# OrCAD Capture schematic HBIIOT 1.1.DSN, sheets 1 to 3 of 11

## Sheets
1 POWER: size C; title: POWER; rev: 2.5.0
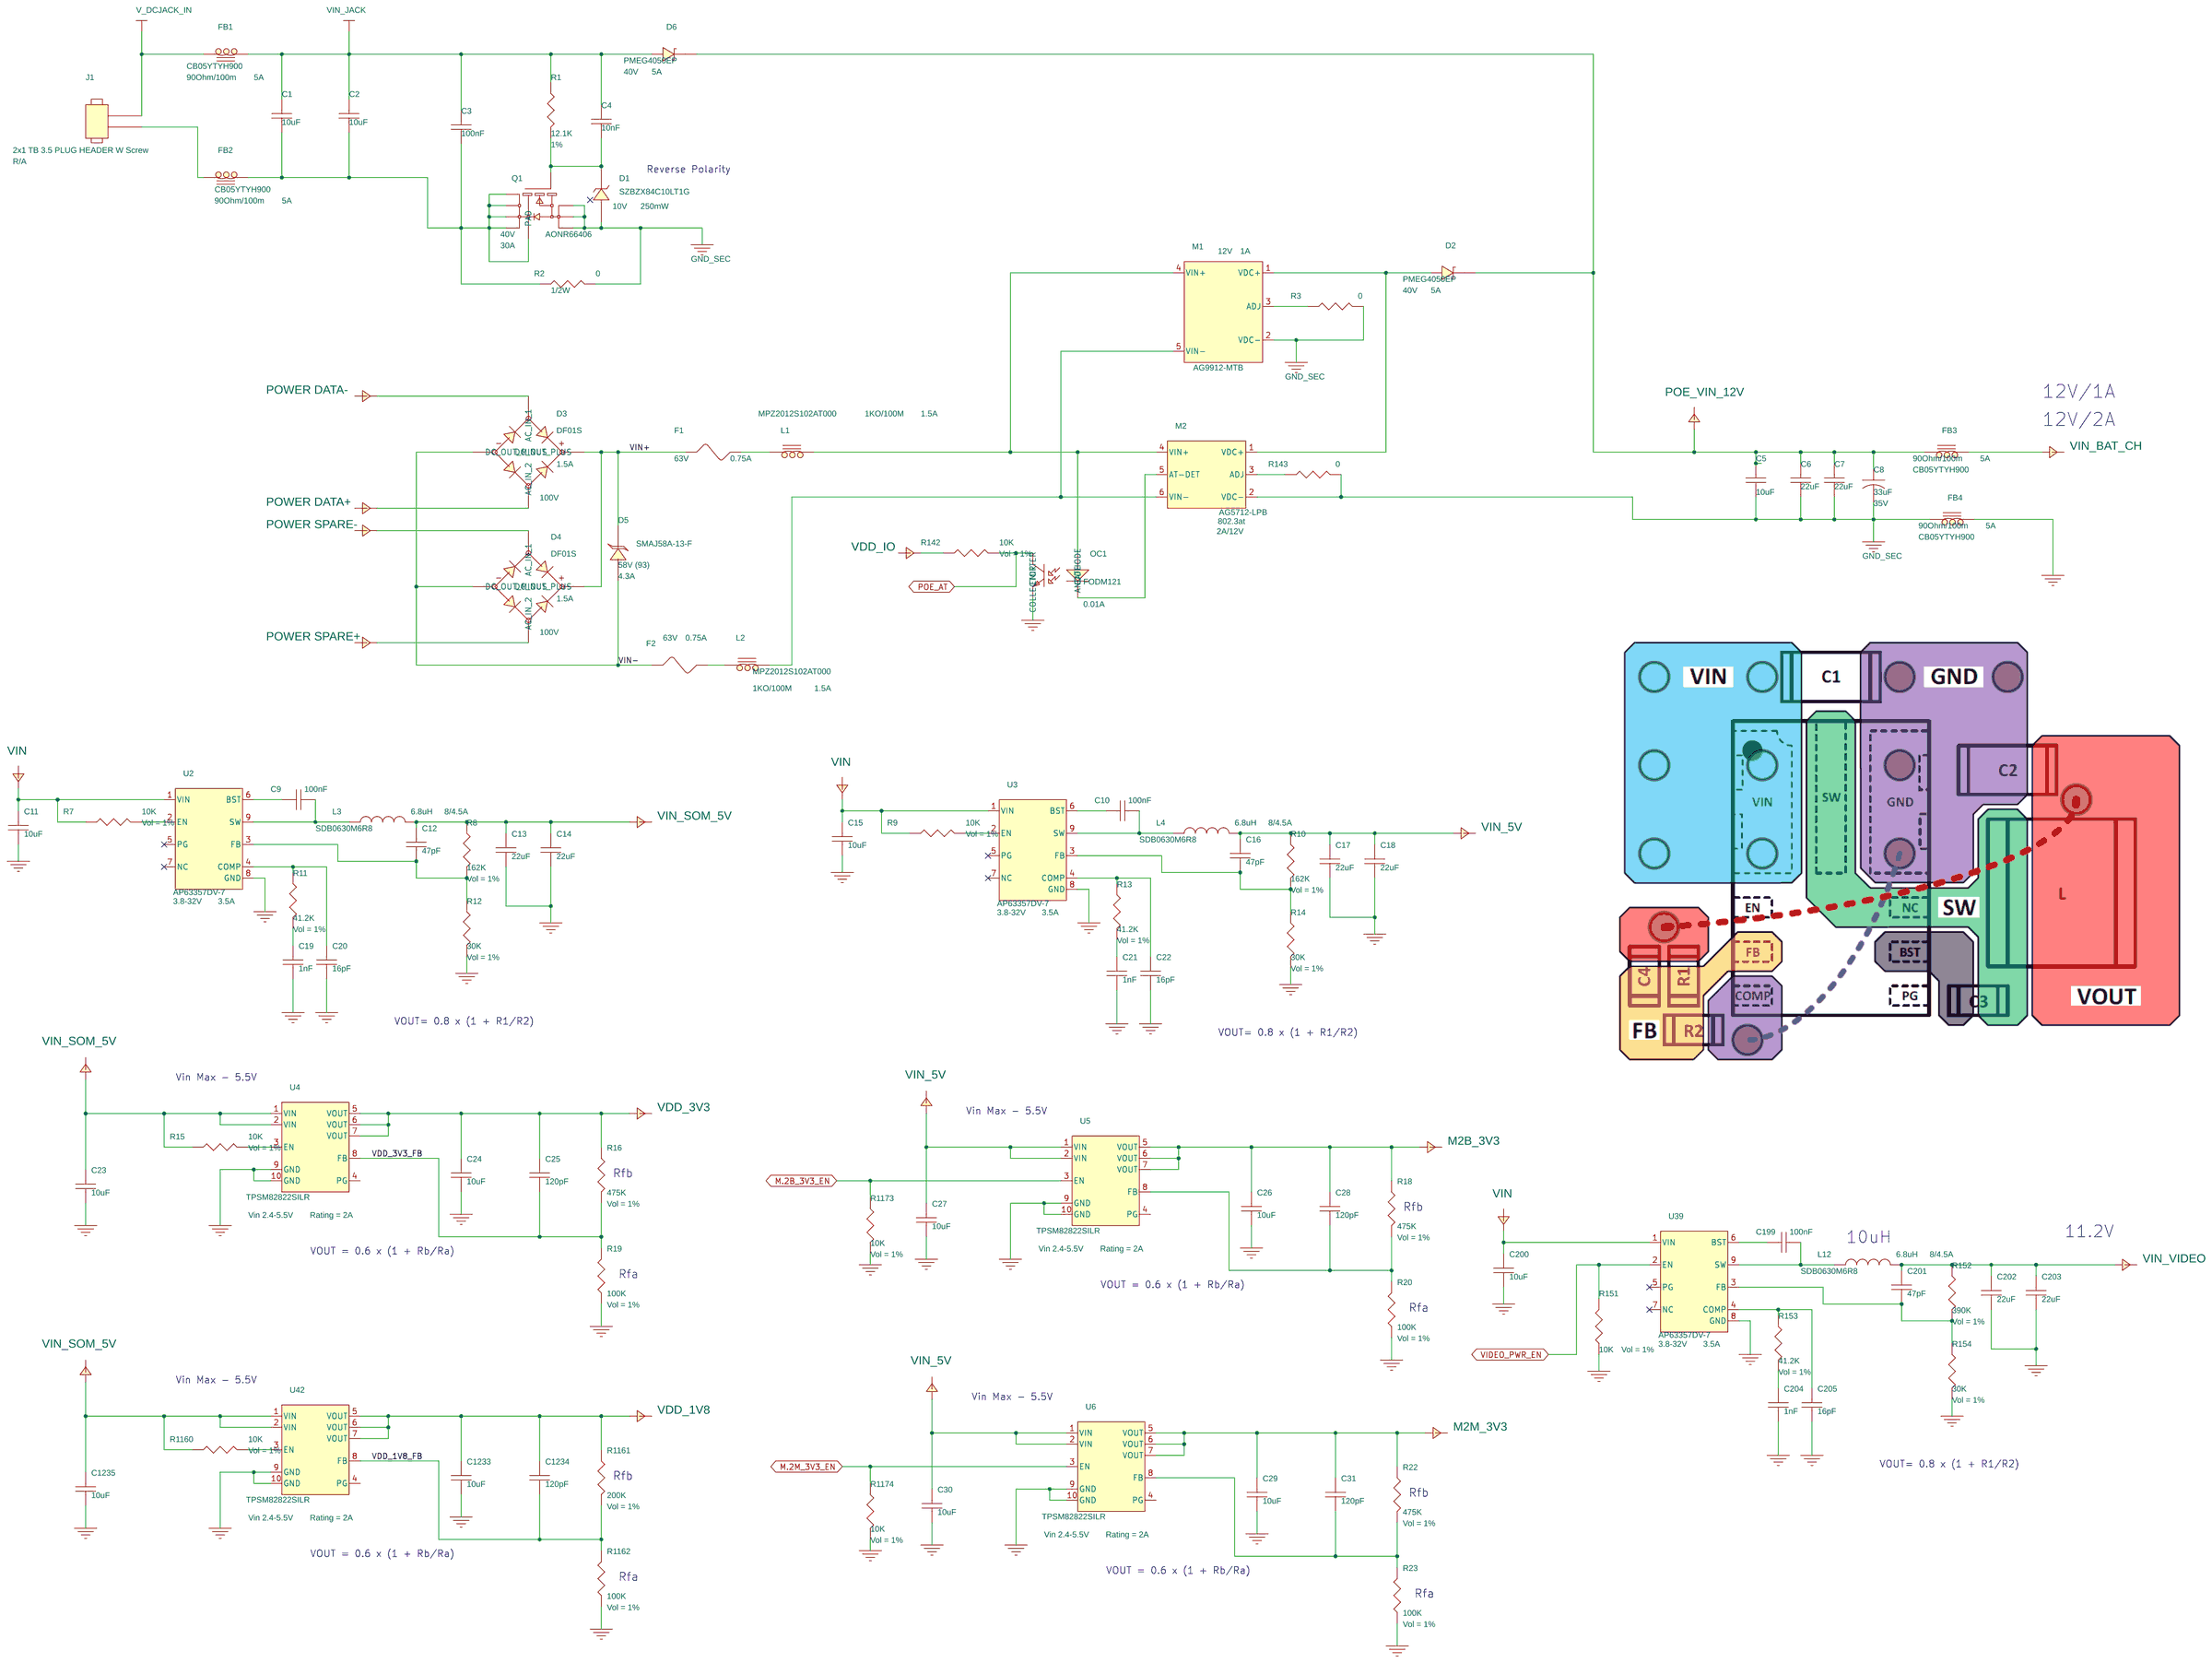
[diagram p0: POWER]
2 SYSTEM, ETHERNET, UART: size A3; title: SYSTEM,  DEBUG, uSD, EEPROM
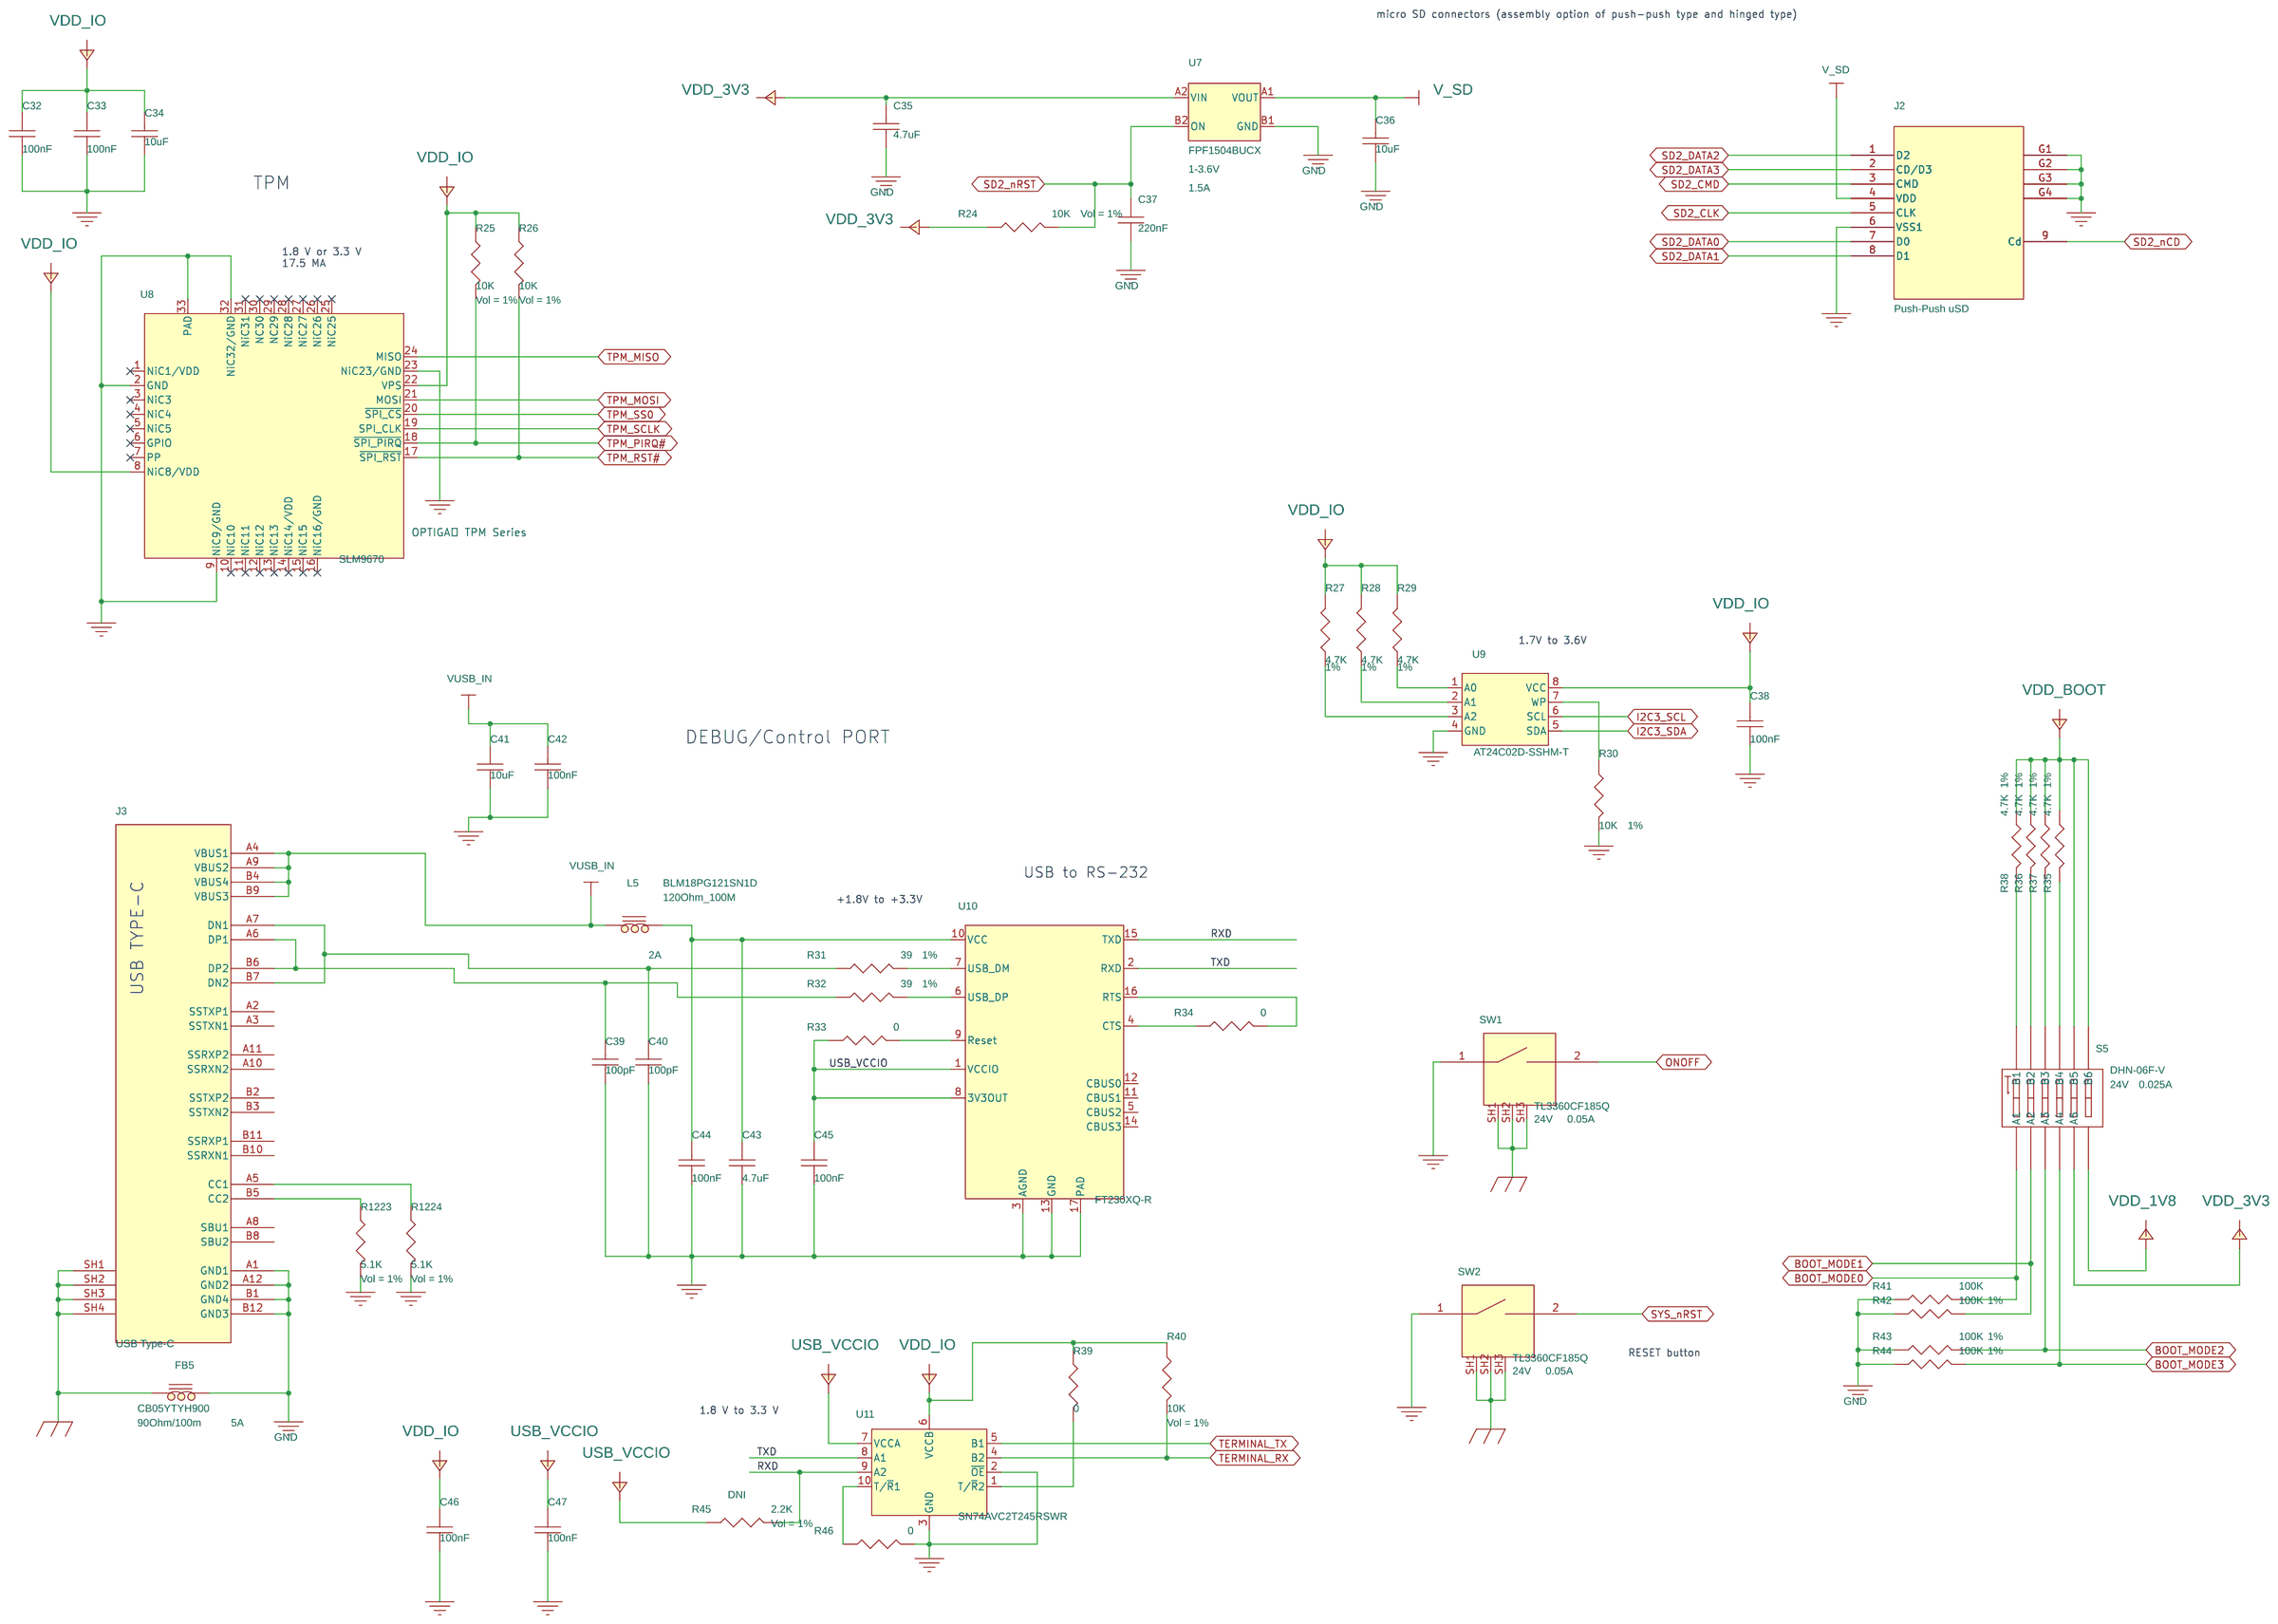
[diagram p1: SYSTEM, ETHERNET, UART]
3 USB3 HUB: size C; title: USB-3 HIB; rev: 2.4.0
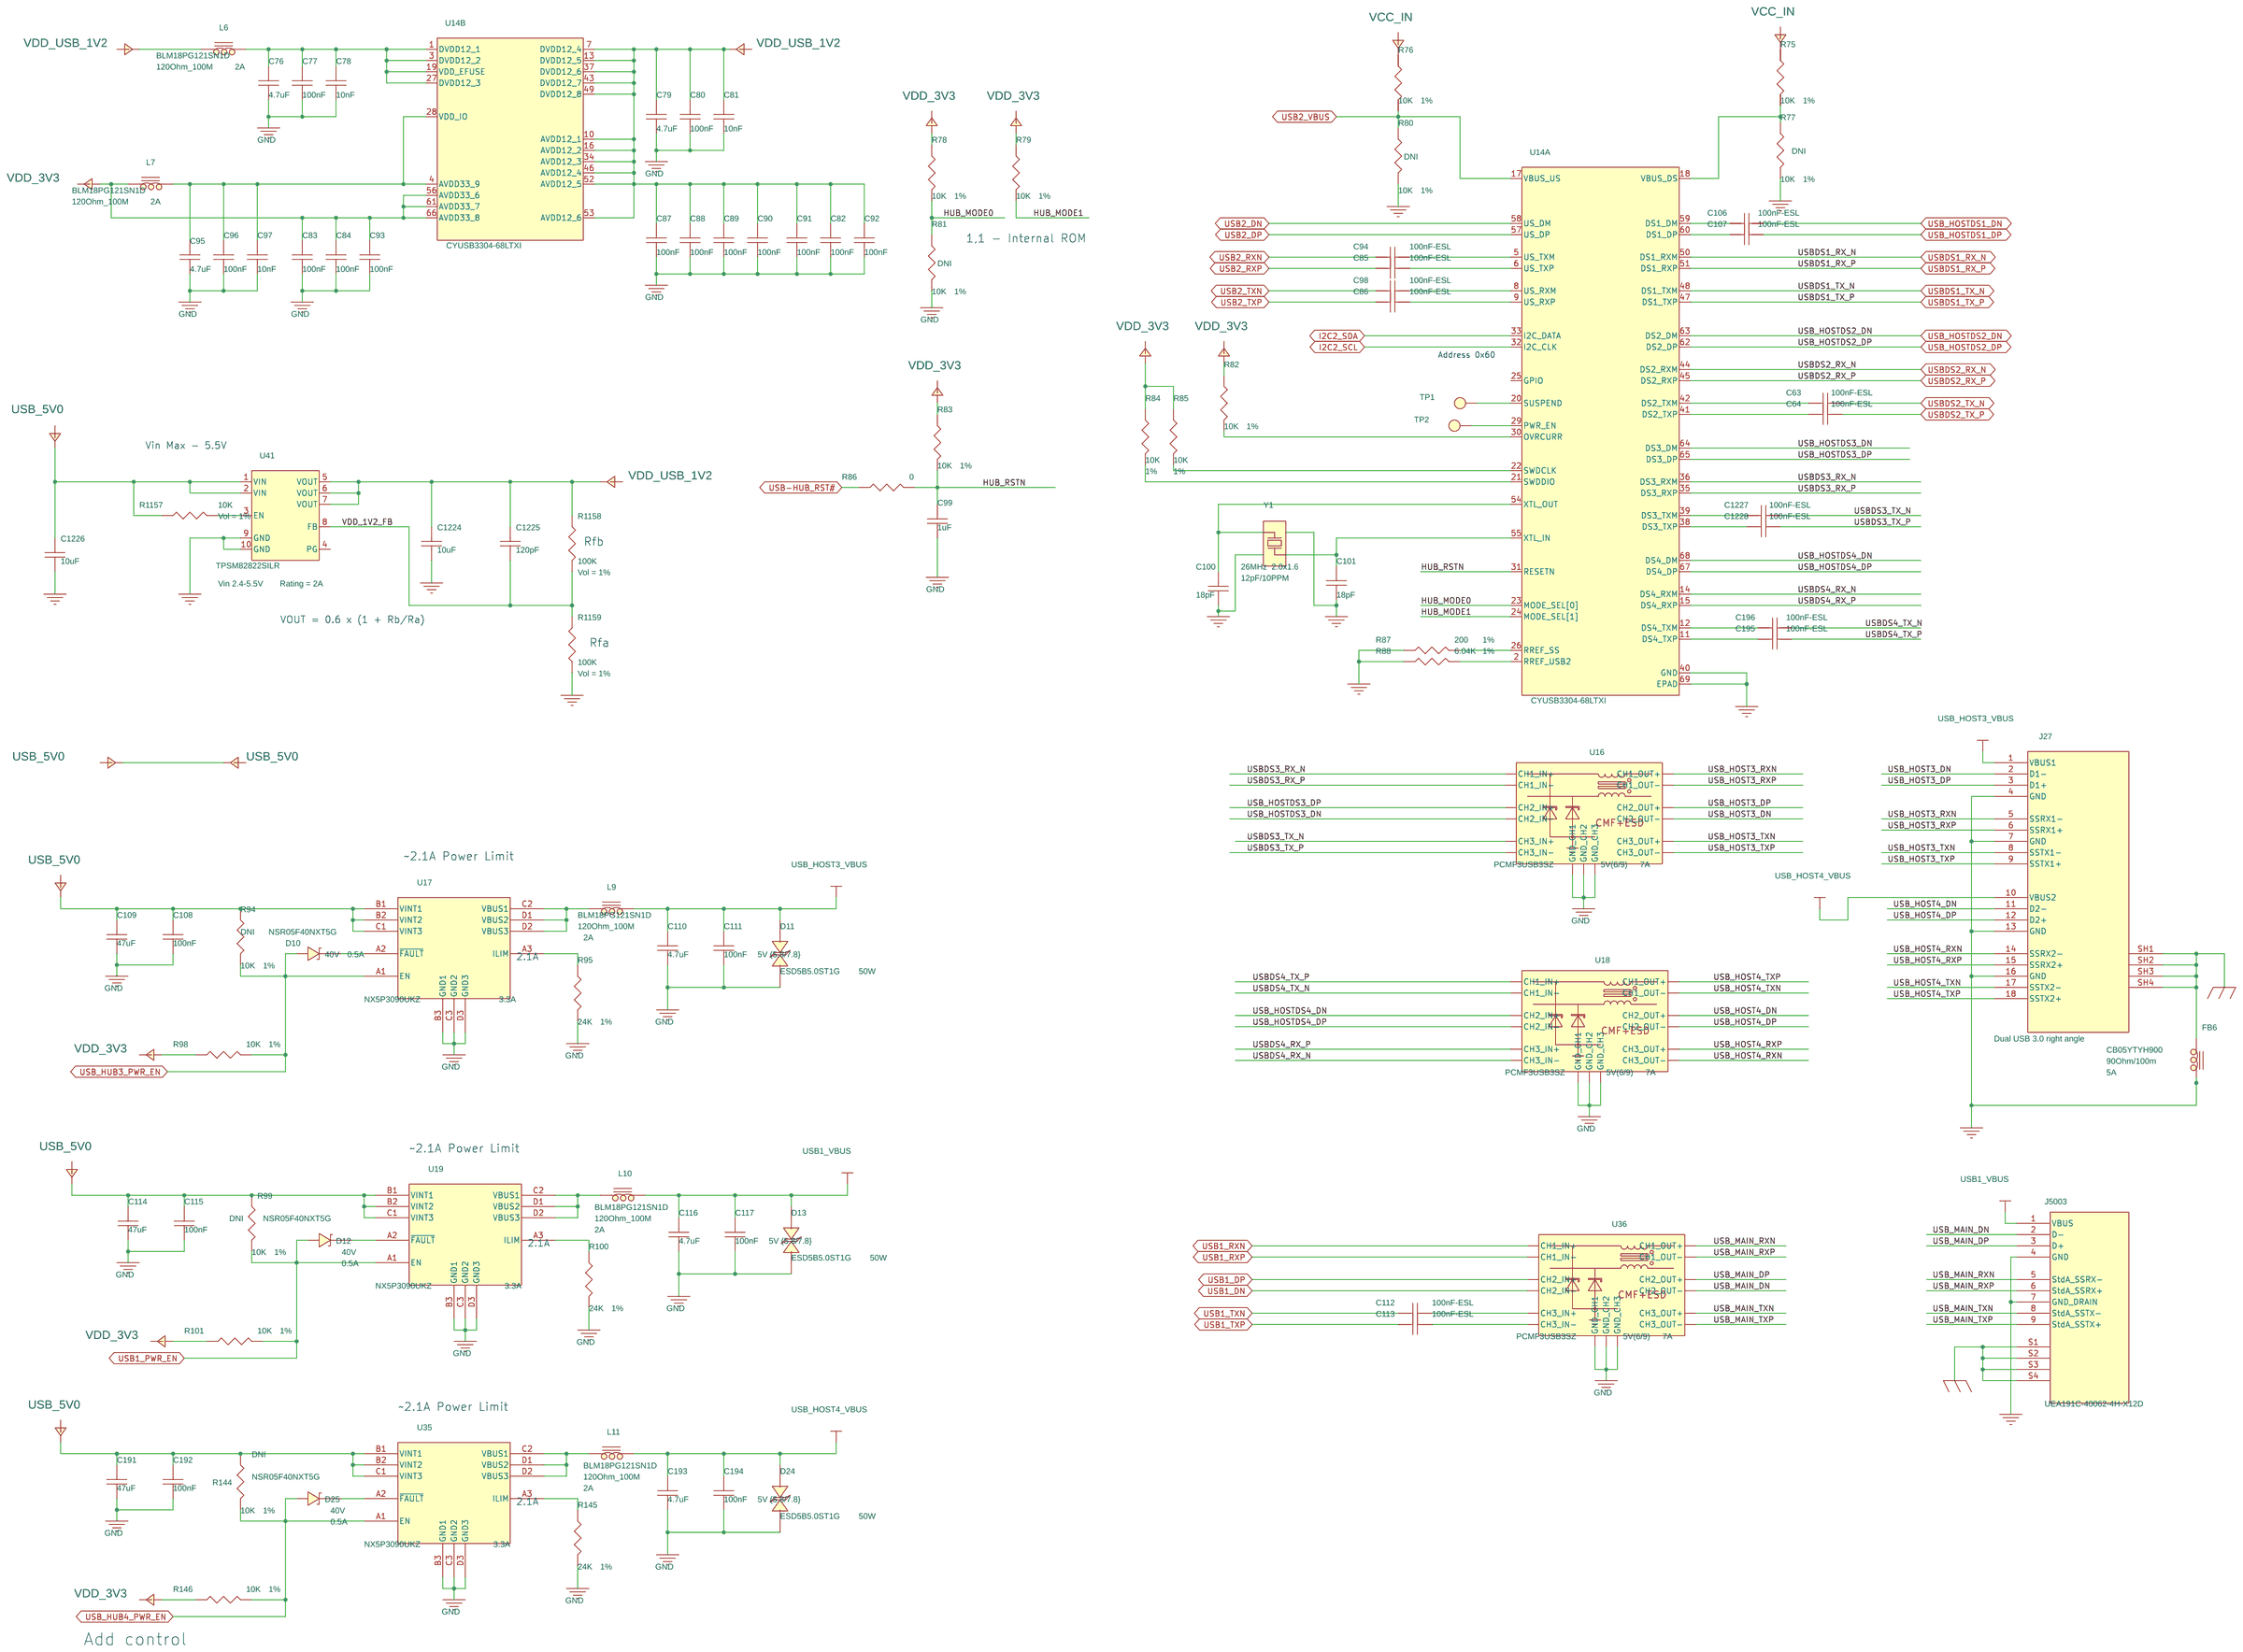
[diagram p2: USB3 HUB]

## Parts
sheet POWER
C1  10uF  [C1206]
C2  10uF  [C1206]
C3  100nF  [C0402]
C4  10nF  [C0402]
C5  10uF  [C0805]
C6  22uF  [C0805]
C7  22uF  [C0805]
C8  33uF  [EEE-FP1E330AP]
C9  100nF  [C0402]
C10  100nF  [C0402]
C11  10uF  [C1206]
C12  47pF  [C0402]
C13  22uF  [C0805]
C14  22uF  [C0805]
C15  10uF  [C1206]
C16  47pF  [C0402]
C17  22uF  [C0805]
C18  22uF  [C0805]
C19  1nF  [C0402]
C20  16pF  [C0402]
C21  1nF  [C0402]
C22  16pF  [C0402]
C23  10uF  [C0402]
C24  10uF  [C0402]
C25  120pF  [C0402]
C26  10uF  [C0402]
C27  10uF  [C0402]
C28  120pF  [C0402]
C29  10uF  [C0402]
C30  10uF  [C0402]
C31  120pF  [C0402]
C199  100nF  [C0402]
C200  10uF  [C1206]
C201  47pF  [C0402]
C202  22uF  [C0805]
C203  22uF  [C0805]
C204  1nF  [C0402]
C205  16pF  [C0402]
C1233  10uF  [C0402]
C1234  120pF  [C0402]
C1235  10uF  [C0402]
D1  SZBZX84C10LT1G  [SZBZX84C10LT1G]
D2  PMEG4050EP  [PMEG4050EP]
D3  DF01S  [DF01S]
D4  DF01S  [DF01S]
D5  SMAJ58A-13-F  [SMAJ58A-13-F]
D6  PMEG4050EP  [PMEG4050EP]
F1  63V  [0437.750WR]
F2  63V  [0437.750WR]
FB1  CB05YTYH900  [CB05YTYH900]
FB2  CB05YTYH900  [CB05YTYH900]
FB3  CB05YTYH900  [CB05YTYH900]
FB4  CB05YTYH900  [CB05YTYH900]
J1  2x1 TB 3.5 PLUG HEADER W Screw  [691325110002]
L1  MPZ2012S102AT000  [MPZ2012S102AT000]
L2  MPZ2012S102AT000  [MPZ2012S102AT000]
L3  SDB0630M6R8  [SDB0630M6R8]
L4  SDB0630M6R8  [SDB0630M6R8]
L12  SDB0630M6R8  [SDB0630M6R8]
M1  AG9912-MTB  [AG9912-MTB]
M2  AG5712-LPB  [AG5712-LPB]
OC1  FODM121  [FODM121]
Q1  AONR66406  [AONR66406]
R1  12.1K  [R0402]
R2  0  [R0603]
R3  0  [R0402]
R7  10K  [R0402]
R8  162K  [R0402]
R9  10K  [R0402]
R10  162K  [R0402]
R11  41.2K  [R0402]
R12  30K  [R0402]
R13  41.2K  [R0402]
R14  30K  [R0402]
R15  10K  [R0402]
R16  475K  [R0402]
R18  475K  [R0402]
R19  100K  [R0402]
R20  100K  [R0402]
R22  475K  [R0402]
R23  100K  [R0402]
R142  10K  [R0402]
R143  0  [R0402]
R151  10K  [R0402]
R152  390K  [R0402]
R153  41.2K  [R0402]
R154  30K  [R0402]
R1160  10K  [R0402]
R1161  200K  [R0402]
R1162  100K  [R0402]
R1173  10K  [R0402]
R1174  10K  [R0402]
U2  AP63357DV-7  [AP63357DV-7]
U3  AP63357DV-7  [AP63357DV-7]
U4  TPSM82822SILR  [TPSM82822SILR]
U5  TPSM82822SILR  [TPSM82822SILR]
U6  TPSM82822SILR  [TPSM82822SILR]
U39  AP63357DV-7  [AP63357DV-7]
U42  TPSM82822SILR  [TPSM82822SILR]
sheet SYSTEM, ETHERNET, UART
C32  100nF  [C0402]
C33  100nF  [C0402]
C34  10uF  [C0402]
C35  4.7uF  [C0402]
C36  10uF  [C0603]
C37  220nF  [C0402]
C38  100nF  [C0402]
C39  100pF  [C0402]
C40  100pF  [C0402]
C41  10uF  [C0603]
C42  100nF  [C0402]
C43  4.7uF  [C0603]
C44  100nF  [C0402]
C45  100nF  [C0402]
C46  100nF  [C0402]
C47  100nF  [C0402]
FB5  CB05YTYH900  [CB05YTYH900]
J2  Push-Push uSD  [ZM90-15000-0BR1]
J3  USB Type-C  [1054500101]
L5  BLM18PG121SN1D  [BLM18PG121SN1D]
R24  10K  [R0402]
R25  10K  [R0402]
R26  10K  [R0402]
R27  4.7K  [R0402]
R28  4.7K  [R0402]
R29  4.7K  [R0402]
R30  10K  [R0402]
R31  39  [R0402]
R32  39  [R0402]
R33  0  [R0402]
R34  0  [R0402]
R35  4.7K  [R0402]
R36  4.7K  [R0402]
R37  4.7K  [R0402]
R38  4.7K  [R0402]
R39  0  [R0402]
R40  10K  [R0402]
R41  100K  [R0402]
R42  100K  [R0402]
R43  100K  [R0402]
R44  100K  [R0402]
R45  2.2K  [R0402]
R46  0  [R0402]
R1223  5.1K  [R0402]
R1224  5.1K  [R0402]
S5  DHN-06F-V  [DHN-06F-V]
SW1  TL3360CF185Q  [TL3360CF185Q]
SW2  TL3360CF185Q  [TL3360CF185Q]
U7  FPF1504BUCX  [FPF1504BUCX]
U8  SLM9670  [SLM9670]
U9  AT24C02D-SSHM-T  [AT24C02D-SSHM-B]
U10  FT230XQ-R  [FT230XQ-R]
U11  SN74AVC2T245RSWR  [SN74AVC2T245RSWR]
sheet USB3 HUB
C63  100nF-ESL  [C0402]
C64  100nF-ESL  [C0402]
C76  4.7uF  [C0603]
C77  100nF  [C0402]
C78  10nF  [C0402]
C79  4.7uF  [C0603]
C80  100nF  [C0402]
C81  10nF  [C0402]
C82  100nF  [C0402]
C83  100nF  [C0402]
C84  100nF  [C0402]
C85  100nF-ESL  [C0402]
C86  100nF-ESL  [C0402]
C87  100nF  [C0402]
C88  100nF  [C0402]
C89  100nF  [C0402]
C90  100nF  [C0402]
C91  100nF  [C0402]
C92  100nF  [C0402]
C93  100nF  [C0402]
C94  100nF-ESL  [C0402]
C95  4.7uF  [C0603]
C96  100nF  [C0402]
C97  10nF  [C0402]
C98  100nF-ESL  [C0402]
C99  1uF  [C0402]
C100  18pF  [C0402]
C101  18pF  [C0402]
C106  100nF-ESL  [C0402]
C107  100nF-ESL  [C0402]
C108  100nF  [C0402]
C109  47uF  [C1206]
C110  4.7uF  [C0603]
C111  100nF  [C0402]
C112  100nF-ESL  [C0402]
C113  100nF-ESL  [C0402]
C114  47uF  [C1206]
C115  100nF  [C0402]
C116  4.7uF  [C0603]
C117  100nF  [C0402]
C191  47uF  [C1206]
C192  100nF  [C0402]
C193  4.7uF  [C0603]
C194  100nF  [C0402]
C195  100nF-ESL  [C0402]
C196  100nF-ESL  [C0402]
C1224  10uF  [C0402]
C1225  120pF  [C0402]
C1226  10uF  [C0402]
C1227  100nF-ESL  [C0402]
C1228  100nF-ESL  [C0402]
D10  NSR05F40NXT5G  [NSR05F40NXT5G]
D11  ESD5B5.0ST1G  [ESD5B5.0ST1G]
D12  NSR05F40NXT5G  [NSR05F40NXT5G]
D13  ESD5B5.0ST1G  [ESD5B5.0ST1G]
D24  ESD5B5.0ST1G  [ESD5B5.0ST1G]
D25  NSR05F40NXT5G  [NSR05F40NXT5G]
FB6  CB05YTYH900  [CB05YTYH900]
J27  Dual USB 3.0 right angle  [U3AFR03-B-P/L-B-G0-A]
J5003  UEA191C-40062-4H-X12D  [UEA191C-40062-4H-X12D]
L6  BLM18PG121SN1D  [BLM18PG121SN1D]
L7  BLM18PG121SN1D  [BLM18PG121SN1D]
L9  BLM18PG121SN1D  [BLM18PG121SN1D]
L10  BLM18PG121SN1D  [BLM18PG121SN1D]
L11  BLM18PG121SN1D  [BLM18PG121SN1D]
R75  10K  [R0402]
R76  10K  [R0402]
R77  10K  [R0402]
R78  10K  [R0402]
R79  10K  [R0402]
R80  10K  [R0402]
R81  10K  [R0402]
R82  10K  [R0402]
R83  10K  [R0402]
R84  10K  [R0402]
R85  10K  [R0402]
R86  0  [R0402]
R87  200  [R0402]
R88  6.04K  [R0402]
R94  10K  [R0402]
R95  24K  [R0402]
R98  10K  [R0402]
R99  10K  [R0402]
R100  24K  [R0402]
R101  10K  [R0402]
R144  10K  [R0402]
R145  24K  [R0402]
R146  10K  [R0402]
R1157  10K  [R0402]
R1158  100K  [R0402]
R1159  100K  [R0402]
TP1  R 35
TP2  R 35
U14  CYUSB3304-68LTXI  [CYUSB3304-68LTXI]  (sections A,B)
U16  PCMF3USB3SZ  [PCMF3USB3SZ]
U17  NX5P3090UKZ  [NX5P3090UKZ]
U18  PCMF3USB3SZ  [PCMF3USB3SZ]
U19  NX5P3090UKZ  [NX5P3090UKZ]
U35  NX5P3090UKZ  [NX5P3090UKZ]
U36  PCMF3USB3SZ  [PCMF3USB3SZ]
U41  TPSM82822SILR  [TPSM82822SILR]
Y1  26MHz  2.0x1.6  [FA-128 26.0000MF10Z-W5]

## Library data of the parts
C1 C2 = CAP_NP1: CAP CER 10uF ±10% 50V X5R 1206; Category : Capacitors (Size: 1206); Digikey P/N: 490-5961-1-ND; Manufacturer: Murata Electronics North America; Part Num#: GRM31CR61H106KA12L; Rating: 50V; SolidRun P/N: CA50004; Vol: 10%
C3 = CAP_NP1: CAP CER 0.1uF ±10% 50V X7R 0402; Category: Capacitors (Size: 0402); Digikey P/N: 490-10700-1-ND; Manufacturer: Murata Electronics North America; Part Num#: GRM155R71H104KE14D; Rating: 50V; SolidRun P/N: CA20147; Vol: 10%
C4 = CAP_NP1: CAP CER 10nF ±10% 25V X7R 0402; Category: Capacitors (Size: 0402); Manufacturer: CAPAX; Part Num#: 0402X103K250SNT; Rating: 25V; SolidRun P/N: CA20002; Vol: 10%
C5 = CAP_NP1: CAP CER 10uF ±10% 25V X5R 0805; Category : Capacitors (Size: 0805); Digikey P/N: 490-5523-1-ND; Manufacturer: Murata Electronics North America; Part Num#: GRM21BR61E106KA73L; Rating: 25V; SolidRun P/N: CA40005; Vol: 10%
C6 C7 C13 C14 C17 C18 C202 C203 = CAP_NP1: CAP CER 22uF ±20% 25V X5R 0805; Digikey P/N: 490-14661-1-ND; Manufacturer: Murata Electronics North America; Part Num#: GRM21BR61E226ME44K; Rating: 25V; SolidRun P/N: CA40011; Vol: 20%
C8 = CAP1: 33µF 25V Aluminum Electrolytic Capacitors Radial, Can - SMD 260 mOhm @ 100kHz 2000 Hrs @ 105°C; Digikey P/N: PCE4541TR-ND; Manufacturer: Panasonic Electronic Components; Rating: 35V; SolidRun P/N: CA90020; Vol: 20%
C9 C10 C199 = CAP_NP1: CAP CER 0.1uF ±10% 16V X7R 0402; Digikey P/N: 1276-1001-1-ND; Manufacturer: Samsung Electro-Mechanics; Part Num#: CL05B104KO5NNNC; Rating: 16V; SolidRun P/N: CA20013; Vol: 10%
C11 C15 C200 = CAP_NP1: CAP CER 10uF ±10% 50V X5R 1206; Digikey P/N: 490-5961-1-ND; Manufacturer: Murata Electronics North America; Part Num#: GRM31CR61H106KA12L; Rating: 50V; SolidRun P/N: CA50004; Vol: 10%
C12 C16 C201 = CAP_NP1: CAP CER 47pF ±5% 50V C0G/NP0 0402; Digikey P/N: 490-1287-6-ND; Manufacturer: Murata Electronics North America; Part Num#: GRM1555C1H470JZ01D; Rating: 50V; SolidRun P/N: CA20144; Vol: 5%
C19 C21 C204 = CAP_NP1: CAP CER 1000pF ±10% 50V X7R 0402; Digikey P/N: 1276-1032-1-ND; Manufacturer: Samsung Electro-Mechanics; Part Num#: CL05B102KB5NNNC; Rating: 50V; SolidRun P/N: CA20008; Vol: 10%
C20 C22 C205 = CAP_NP1: CAP CER 16pF ±5% 50V C0G/NP0 0402; Digikey P/N: 1276-1646-1-ND; Manufacturer: Samsung Electro-Mechanics; Part Num#: CL05C160JB5NNNC; Rating: 50V; SolidRun P/N: CA20134; Vol: 5%
C23 C24 C26 C27 C29 C30 C34 C1224 C1226 C1233 C1235 = CAP_NP1: CAP CER 10uF ±20% 6.3V X6S 0402; Digikey P/N: 490-13233-1-ND; Manufacturer: Murata Electronics North America; Part Num#: GRM155C80J106ME11D; Rating: 6.3V; SolidRun P/N: CA20131; Vol: 20%
C25 C28 C31 C1225 C1234 = CAP_NP1: CAP CER 120PF 50V NPO 0402; Digikey P/N: 311-3337-2-ND; Manufacturer: Yageo; Part Num#: CC0402JRNPO9BN121; Rating: 50V; SolidRun P/N: CA20830; Vol: 5%
D1 = DIODE_ZENER_SOT23-3: Zener Diode 10V 225mW ±6% Surface Mount SOT-23-3 (TO-236; Category: DI-Zener; Digikey P/N: SZBZX84C10LT1GOSTR-ND; Manufacturer: ON Semiconductor; Rating: 250mW; SolidRun P/N: DI00205; Vol: 10V; Datasheet: https://www.onsemi.com/pub/Collateral/BZX84C2V4LT1-D.PDF
D2 D6 = Diode-STK-OLD: DIODE SCHOTTKY 40V 5A CFP5; Digikey P/N: 1727-5842-2-ND; Manufacturer: Nexperia USA Inc.; Rating: 5A; SolidRun P/N: DI00286; Vol: 40V; Datasheet: https://assets.nexperia.com/documents/data-sheet/PMEG4050EP.pdf
D3 D4 = D-DF01S-Bridge: IC RECT BRIDGE 100V 1.5A 4-SMD; Category : DI-Diode; Digikey P/N: DF01STR-ND; Manufacturer: ON Semiconductor; Rating: 1.5A; SolidRun P/N: DI00235; Vol: 100V; Datasheet: https://www.fairchildsemi.com/datasheets/DF/DF005S.pdf
D5 = TVS-UNI-OLD: TVS DIODE 58VWM 93.6VC SMA; Digikey P/N: SMAJ58A-13-FDITR-ND; Manufacturer: Diodes Incorporated; Rating: 4.3A; SolidRun P/N: DI00244; Vol: 58V (93); Datasheet: https://www.diodes.com/assets/Datasheets/ds19005.pdf
F1 F2 = FUSE1: 750 mA 63 V AC 63 V DC Fuse Board Mount (Cartridge Style Excluded) Surface Mount 1206 (3216 Metric); Digikey P/N: F2880TR-ND; Manufacturer: Littelfuse Inc.; Rating: 0.75A; SolidRun P/N: FS00035; Datasheet: https://www.littelfuse.com/~/media/electronics/datasheets/fuses/littelfuse_fuse_437_datasheet.pdf.pdf
FB1 FB2 FB6 = Ferrite_Bead: Filter Bead 90ohms 25% 0805 HighCurrent,RatedCurrent=3A; Category : COILS-FERRIT; Digikey P/N: 541-2303-2-ND; Manufacturer: VIKING; Rating: 5A; SolidRun P/N: IN00001; Vol: 90Ohm/100m; Datasheet: https://www.viking.com.tw/Templates/att/CBM_Series.pdf?lng=en
FB3 FB4 = Ferrite_Bead: Filter Bead 90ohms 25% 0805 HighCurrent,RatedCurrent=3A; Category: COILS-FERRIT; Category : COILS-FERRIT; Digikey P/N: 541-2303-2-ND; Manufacturer: VIKING; Rating: 5A; SolidRun P/N: IN00001; Vol: 90Ohm/100m; Datasheet: https://www.viking.com.tw/Templates/att/CBM_Series.pdf?lng=en
J1 = J-TB2: SERIE 3251 - 2x1 3.50MM HORIZONTAL PCB HEADER WITH FLANGES WR-TB; Manufacturer: Wurth Electronics; SolidRun P/N: CO00768; Vol: R/A; Datasheet: https://katalog.we-online.com/em/datasheet/6913251100xx.pdf
L1 L2 = Ferrite_Bead: 1 kOhms @ 100MHz 1 Power Line Ferrite Bead 0805 (2012 Metric) 1.5A 150mOhm; Category: COILS-FERRIT; Category : COILS-FERRIT; Digikey P/N: 445-5223-2-ND; Manufacturer: TDK Corporation; Rating: 1.5A; SolidRun P/N: IN00128; Vol: 1KO/100M; Datasheet: https://product.tdk.com/info/en/catalog/datasheets/beads_commercial_power_mpz2012_en.pdf
L3 L4 L12 = INDUCTOR1: IND 6.8uH 6.8 x 7.6 x 3.0 60mOhm 8/4.5A; Manufacturer: VIKING; Rating: 8/4.5A; SolidRun P/N: IN00067; Vol: 6.8uH; Datasheet: https://www.viking.com.tw/Templates/att/SDB_REV_B5-160912.pdf?lng=en
M1 = M-AG9912-MTB-POE: Power over Ethernet - PoE PD Module, Isolated DC-DC converter, IEEE802.3af compliant, Over Temp. Protection, Ind Temp. Range, Small Footprint, SMT. (Blocks not pins).; Manufacturer: Silvertel; Rating: 1A; SolidRun P/N: IC01852; Vol: 12V; Datasheet: https://silvertel.com/images/datasheets/Ag9900M-datasheet-ultra-miniature-isolated-Power-over-Ethernet-POE-module.pdf
M2 = M-AG57xxLPB-POE: Miniature 802.3at SMT POE+ with DC-DC12V/24W; Digikey P/N: 480-AG5712-LPB; Manufacturer: Silvertel; Part Num#: 5061-AG5712-LPB-ND; Rating: 2A/12V; SolidRun P/N: IC01920; Vol: 802.3at; Datasheet: https://silvertel.com/images/datasheets/Ag5700LPB-datasheet-minature%20IEEE802_3At%2024W%20power-over-ethernet%20module.pdf
OC1 = OPTC-DC-4P: Optoisolator Transistor Output 3750Vrms 1 Channel 4-Mini-Flat; Category: IC-INT-OPT; Digikey P/N: FODM121-ND; Manufacturer: ON Semiconductor; Rating: 0.01A; SolidRun P/N: IC01209; VOL: 1.4V; Datasheet: https://www.fairchildsemi.com/datasheets/FO/FODM121.pdf
Q1 = MOSFET_N_DFN: 40V N-Channel AlphaSGT 30A; Category: TR-MOSFET-N; Digikey P/N: AONR66406-ND; Manufacturer: Alpha & Omega Semiconductor Inc; Rating: 30A; SolidRun P/N: TR00018; Vol: 40V; Datasheet: http://aosmd.com/res/data_sheets/AONR66406.pdf
R1 = RES1: RES SMD 12.1K OHM 1% 1/16W 0402; Category: Resistors (Size: 0402); Digikey P/N: 311-12.1KLRCT-ND; Manufacturer: YAGEO; Part Num#: RC0402FR-0712K1L; Rating: 1/16W; SolidRun P/N: RE20433; Vol: 1%
R2 = RES1: RES SMD 0 OHM JUMPER 1/2W 0603; Category: Resistors (Size: 0603); Digikey P/N: 36-5110CT-ND; Manufacturer: Keystone Electronics; Part Num#: 5110; Rating: 1/2W; SolidRun P/N: RE30017
R3 R39 R46 R143 = RES1: RES SMD 0 OHM JUMPER 1/16W 0402; Digikey P/N: 311-0.0JRCT-ND; Manufacturer: YAGEO; Part Num#: RC0402JR-070RL; Rating: 1/16W; SolidRun P/N: RE20009
R7 R9 R15 R24-R26 R142 R151 R1157 R1160 R1173 R1174 = RES1: RES SMD 10K OHM 1% 1/16W 0402; Digikey P/N: 311-10.0KLRCT-ND; Manufacturer: YAGEO; Part Num#: RC0402FR-0710KL; Rating: 1/16W; SolidRun P/N: RE20013; Vol: 1%
R8 R10 = RES1: RES SMD 162K OHM 1% 1/16W 0402; Digikey P/N: YAG2370TR-ND; Manufacturer: YAGEO; Part Num#: RC0402FR-07162KL; Rating: 1/16W; SolidRun P/N: RE20539; Vol: 1%
R11 R13 R153 = RES1: RES SMD 41.2K OHM 1% 1/16W 0402; Digikey P/N: YAG3155CT-ND; Manufacturer: YAGEO; Part Num#: RC0402FR-0741K2L; Rating: 1/16W; SolidRun P/N: RE20409; Vol: 1%
R12 R14 R154 = RES1: RES SMD 30K OHM 1% 1/16W 0402; Digikey P/N: 311-30.0KLRCT-ND; Manufacturer: YAGEO; Part Num#: RC0402FR-0730KL; Rating: 1/16W; SolidRun P/N: RE20458; Vol: 1%
R16 R18 R22 = RES1: RES SMD 475K OHM 1% 1/16W 0402; Digikey P/N: 311-475KLRCT-ND; Manufacturer: YAGEO; Part Num#: RC0402FR-07475KL; Rating: 1/16W; SolidRun P/N: RE20018; Vol: 1%
R19 R20 R23 R1158 R1159 R1162 = RES1: RES SMD 100K OHM 1% 1/16W 0402; Digikey P/N: 311-100KLRCT-ND; Manufacturer: YAGEO; Part Num#: RC0402FR-07100KL; Rating: 1/16W; SolidRun P/N: RE20482; Vol: 1%
R152 = RES1: RES 390K OHM 1% 1/16W 0402; Digikey P/N: YAG3143TR-ND; Manufacturer: YAGEO; Part Num#: RC0402FR-07390KL; Rating: 1/16W; SolidRun P/N: RE20581; Vol: 1%
R1161 = RES1: RES SMD 200K OHM 1% 1/16W 0402; Digikey P/N: 311-200KLRCT-ND; Manufacturer: YAGEO; Part Num#: RC0402FR-07200KL; Rating: 1/16W; SolidRun P/N: RE20036; Vol: 1%
U2 U3 U39 = IC-AP63357: Buck Switching Regulator IC Positive Adjustable 0.8V 1 Output 3.5A 13-PowerVFDFN; Digikey P/N: 31-AP63357DV-7TR-ND; Manufacturer: Diodes Incorporated; Rating: 3.5A; SolidRun P/N: IC01538; Vol: 3.8-32V; Datasheet: https://www.diodes.com/assets/Datasheets/AP63356-AP63357.pdf
U4-U6 U41 U42 = IC-TPSM8282x: Non-Isolated PoL Module DC DC Converter 1 Output 0.6 ~ 4V    2A 2.4V - 5.5V Input; Digikey P/N: 296-TPSM82822SILRTR-ND; Manufacturer: Texas Instruments; Rating: 2A; SolidRun P/N: IC01589; Vol: Vin 2.4-5.5V; Datasheet: https://www.ti.com/general/docs/suppproductinfo.tsp?distId=10&gotoUrl=http%3A%2F%2Fwww.ti.com%2Flit%2Fgpn%2Ftpsm82821
C32 C33 = CAP_NP1: CAP CER 0.1uF ±10% 10V X7R 0402; Category: Capacitors (Size: 0402); Digikey P/N: 1276-1002-2-ND; Manufacturer: Samsung Electro-Mechanics; Part Num#: CL05B104KP5NNNC; Rating: 10V; SolidRun P/N: CA20001; Vol: 10%
C35 = CAP_NP1: CAP CER 4.7uF ±20% 6.3V X5R 0402; Digikey P/N: 490-5408-1-ND; Manufacturer: Murata Electronics North America; Part Num#: GRM155R60J475ME87D; Rating: 6.3V; SolidRun P/N: CA20800; Vol: 20%
C36 = CAP_NP1: CAP CER 10uF ±10% 6.3V X5R 0603; Digikey P/N: 1276-1038-1-ND; Manufacturer: Samsung Electro-Mechanics; Part Num#: CL10A106KQ8NNNC; Rating: 6.3V; SolidRun P/N: CA30001; Vol: 10%
C37 = CAP_NP1: CAP CER 0.22uF ±10% 6.3V X5R 0402; Digikey P/N: 490-5407-1-ND; Manufacturer: Murata Electronics North America; Part Num#: GRM155R60J224KE01D; Rating: 6.3V; SolidRun P/N: CA20016; Vol: 10%
C38 C42 C44-C47 C77 C80 C82-C84 C87-C93 C96 C108 C111 C115 C117 C192 C194 = CAP_NP1: CAP CER 0.1uF ±10% 16V X7R 0402; Category : Capacitors (Size: 0402); Digikey P/N: 1276-1001-1-ND; Manufacturer: Samsung Electro-Mechanics; Part Num#: CL05B104KO5NNNC; Rating: 16V; SolidRun P/N: CA20013; Vol: 10%
C39 C40 = CAP_NP1: CAP CER 100pF 50V 5% C0G 0402; Category : Capacitors (Size: 0402); Digikey P/N: 1276-1025-2-ND; Manufacturer: Samsung Electro-Mechanics; Part Num#: CL05C101JB5NNNC; Rating: 50V; SolidRun P/N: CA20006; Vol: 5%
C41 = CAP_NP1: CAP CER 10uF ±10% 16V X5R 0603; Category : Capacitors (Size: 0603); Digikey P/N: 490-10728-2-ND; Manufacturer: Murata Electronics North America; Part Num#: GRM188R61C106KAALD; Rating: 16V; SolidRun P/N: CA30014; Vol: 10%
C43 C110 C116 C193 = CAP_NP1: CAP CER 4.7uF ±10% 10V X5R 0603; Category : Capacitors (Size: 0603); Digikey P/N: 311-1455-1-ND; Manufacturer: YAGEO; Part Num#: CC0603KRX5R6BB475; Rating: 10V; SolidRun P/N: CA30017; Vol: 10%
FB5 = Ferrite_Bead: Filter Bead 90ohms 25% 0805 HighCurrent,RatedCurrent=3A; Digikey P/N: 541-2303-2-ND; Manufacturer: VIKING; Rating: 5A; SolidRun P/N: IN00001; Vol: 90Ohm/100m; Datasheet: https://www.viking.com.tw/Templates/att/CBM_Series.pdf?lng=en
J2 = J-uSD-ZM90: SD/MMC card connector Push-Push/CD; Manufacturer: CEN LINK; SolidRun P/N: CO00091; Datasheet: http://www.cenlink.com.tw/upload/20120718204404.pdf
J3 = J-USB_TYPECRA_MOLEX: CONN RCPT USB C 3.1 SMT R/A; Digikey P/N: WM12856TR-ND; Manufacturer: Molex, LLC; SolidRun P/N: CO00643; Datasheet: https://www.molex.com/pdm_docs/sd/1054500101_sd.pdf
L5-L7 L9-L11 = Ferrite_Bead: Bead 120ohm, 100MHz, 2A; Category : COILS-FERRIT; Digikey P/N: 490-1037-2-ND; Manufacturer: Murata Electronics North America; Rating: 2A; SolidRun P/N: IN00003; Vol: 120Ohm_100M; Datasheet: https://www.murata.com/en-us/products/productdata/8796738650142/ENFA0003.pdf
R27-R29 R35-R38 = RES1: RES SMD 4.7K OHM 1% 1/16W 0402; Category : Resistors (Size: 0402); Digikey P/N: 311-4.7KLRCT-ND; Manufacturer: YAGEO; Part Num#: RC0402FR-074K7L; Rating: 1/16W; SolidRun P/N: RE20497; Vol: 1%
R30 R75 R76 R78 R79 R82-R85 R98 R101 R146 = RES1: RES SMD 10K OHM 1% 1/16W 0402; Category : Resistors (Size: 0402); Digikey P/N: 311-10.0KLRCT-ND; Manufacturer: YAGEO; Part Num#: RC0402FR-0710KL; Rating: 1/16W; SolidRun P/N: RE20013; Vol: 1%
R31 R32 = RES1: RES SMD 39 OHM 1% 1/16W 0402; Category : Resistors (Size: 0402); Digikey P/N: 311-39.0LRCT-ND; Manufacturer: YAGEO; Part Num#: RC0402FR-0739RL; Rating: 1/16W; SolidRun P/N: RE20484; Vol: 1%
R33 R34 R86 = RES1: RES SMD 0 OHM JUMPER 1/16W 0402; Category : Resistors (Size: 0402); Digikey P/N: 311-0.0JRCT-ND; Manufacturer: YAGEO; Part Num#: RC0402JR-070RL; Rating: 1/16W; SolidRun P/N: RE20009
R40 = RES1: RES SMD 10K OHM 1% 1/16W 0402; Category: Resistors (Size: 0402); Digikey P/N: 311-10.0KLRCT-ND; Manufacturer: YAGEO; Part Num#: RC0402FR-0710KL; Rating: 1/16W; SolidRun P/N: RE20013; Vol: 1%
R41-R44 = RES1: RES SMD 100K OHM 1% 1/16W 0402; Category : Resistors (Size: 0402); Digikey P/N: 311-100KLRCT-ND; Manufacturer: YAGEO; Part Num#: RC0402FR-07100KL; Rating: 1/16W; SolidRun P/N: RE20482; Vol: 1%
R45 = RES1: RES SMD 2.2K OHM 1% 1/16W 0402; ASSEMBLY: DNI; BOM_IGNORE: TRUE; Category: Resistors (Size: 0402); Digikey P/N: 311-2.20KLRCT-ND; Manufacturer: YAGEO; Part Num#: RC0402FR-072K2L; Rating: 1/16W; SolidRun P/N: RE20204; Vol: 1%
R1223 R1224 = RES1: RES SMD 5.1K OHM 1% 1/16W 0402; Digikey P/N: 311-5.10KLRCT-ND; Manufacturer: YAGEO; Part Num#: RC0402FR-075K1L; Rating: 1/16W; SolidRun P/N: RE20422; Vol: 1%
S5 = SW-DIP-6_SM: DIP Switches/SIP Switches Half Pitch Dip switch 1.6mm height; Manufacturer: DIPTRONICS MANUFACTURING; Rating: 0.025A; SolidRun P/N: SW00026; Vol: 24V; Datasheet: http://www.dip.com.tw/en/en-product-information/en-switch002/item/2377-dhnf
SW1 SW2 = SW-TACT-2-S: Tactile Switch SPST-NO Side Actuated Surface Mount, Right Angle - 4.0mm actuator pin; Digikey P/N: EG5358CT-ND; Manufacturer: E-Switch; Rating: 0.05A; SolidRun P/N: CO00629; Vol: 24V; Datasheet: https://www.e-switch.com/system/asset/product_line/data_sheet/208/TL3360.pdf
U7 = IC-FPF1504: Power Switch/Driver 1:1 P-Channel 1.5A 4-WLCSP (0.96x0.96); Digikey P/N: FPF1504BUCXCT-ND; Manufacturer: ON Semiconductor; Rating: 1.5A; SolidRun P/N: IC01424; Vol: 1-3.6V; Datasheet: https://www.onsemi.com/pub/Collateral/FPF1504L-D.pdf
U8 = IC-ST33TPHF20SPI-SEC: INDUSTRIAL TPM 2.0 SECURITY; Digikey P/N: SLM9670AQ20FW1311XTMA1TR-ND; Manufacturer: Infineon Technologies; Part Num#: SLM9670AQ20FW1311XTMA1; SolidRun P/N: IC01441; Vol: OPTIGA™ TPM Series; Datasheet: https://www.infineon.com/dgdl/Infineon-SLM%209670-DS-v01_00-EN.pdf?fileId=5546d46269e1c019016a21819cc80c93
U9 = IC-AT24C02D: I2C Compatible Serial EEPROM  2-Kbit (256 x 8); Category : IC-MEM-EEPROM; Digikey P/N: AT24C02D-SSHM-B-ND; Manufacturer: Microchip Technology; SolidRun P/N: IC00927; VOL: 2Kbit; Datasheet: http://www.microchip.com/mymicrochip/filehandler.aspx?ddocname=en590275
U10 = IC-FT230XQ-R: FT230XQ-R - uUSB to UART converter; Category : IC-USB; Digikey P/N: 768-1130-2-ND; Manufacturer: FTDI, Future Technology Devices International Ltd; SolidRun P/N: IC00015; Datasheet: http://www.ftdichip.com/Support/Documents/DataSheets/ICs/DS_FT230X.pdf
U11 = IC-SN74AXC2T245: Voltage Level Translator Bidirectional 1 Circuit 2 Channel 500Mbps 10-UQFN (1.8x1.4); Digikey P/N: 296-23684-2-ND; Manufacturer: Texas Instruments; SolidRun P/N: IC01810; Datasheet: https://www.ti.com/general/docs/suppproductinfo.tsp?distId=10&gotoUrl=https%3A%2F%2Fwww.ti.com%2Flit%2Fgpn%2Fsn74avc2t245
C63 C64 C85 C86 C94 C98 C106 C107 C112 C113 C195 C196 C1227 C1228 = CAP_NP1: CAP CER 0.1uF ±10% 25V X7R 0402; Category : Capacitors (Size: 0402); Manufacturer: CAPAX; Part Num#: 0402X104K250SNT; Rating: 25V; SolidRun P/N: CA20090; Vol: 10%
C76 C79 C95 = CAP_NP1: CAP CER 4.7uF ±10% 6.3V X5R; Category : Capacitors (Size: 0603); Digikey P/N: 1276-1045-2-ND; Manufacturer: Samsung Electro-Mechanics; Part Num#: CL10A475KQ8NNNC; Rating: 6.3V; SolidRun P/N: CA30003; Vol: 10%
C78 C81 C97 = CAP_NP1: CAP CER 0.01uF ±10% 10V X7R 0402; Category : Capacitors (Size: 0402); Digikey P/N: 311-1703-1-ND; Manufacturer: YAGEO; Part Num#: CC0402KRX7R6BB103; Rating: 10V; SolidRun P/N: CA20081; Vol: 10%
C99 = CAP_NP1: CAP CER 1UF 10V X5R 0402; Category : Capacitors (Size: 0402); Digikey P/N: 1276-1076-1-ND; Manufacturer: Samsung Electro-Mechanics; Part Num#: CL05A105KP5NNNC; Rating: 10V; SolidRun P/N: CA20005; Vol: 10%
C100 C101 = CAP_NP1: CAP CER 18pF ±1% 50V C0G/NPO 0402; Category : Capacitors (Size: 0402); Digikey P/N: 311-1643-1-ND; Manufacturer: YAGEO; Part Num#: CC0402FRNPO9BN180; Rating: 50V; SolidRun P/N: CA20017; Vol: 1%
C109 C114 C191 = CAP_NP1: CAP CER 47uF ±20% 10V X5R 1206; Category : Capacitors (Size: 1206); Digikey P/N: 587-3428-1-ND; Manufacturer: Taiyo Yuden; Part Num#: LMK316ABJ476ML-T; Rating: 10V; SolidRun P/N: CA50008; Vol: 20%
D10 D12 D25 = Diode-STK-OLD: DIODE SCHOTTKY 40V 500MA 2DSN; Category : DI-Diode; Digikey P/N: NSR05F40NXT5GOSTR-ND; Manufacturer: ON Semiconductor; Rating: 0.5A; SolidRun P/N: DI00237; Vol: 40V; Datasheet: http://www.onsemi.com/pub/Collateral/NSR05F40-D.PDF
D11 D13 D24 = TVS-BI: TVS DIODE 5VWM SOD523 BI; Category : DI-TVS; Digikey P/N: ESD5B5.0ST1GOSTR-ND; Manufacturer: ON Semiconductor; Rating: 50W; SolidRun P/N: DI00242; Vol: 5V (5.8/7.8}; Datasheet: http://www.onsemi.com/pub/Collateral/ESD5B5.0ST1-D.PDF
J27 = J-Dual_USB3: Category : CON-USB; Manufacturer: Antek (Cidev); SolidRun P/N: CO00554; Datasheet: http://www.antenk.com/cpxx.asp?flag=392&id=1824
J5003 = J-USB3_1: USB 3.0 A Type, Upright, T/H, 9 Pos, Straight Edges; Manufacturer: Foxconn; SolidRun P/N: CO00954; Datasheet: https://drive.google.com/open?id=1X_QLnRV8v2PlPRviEXs41c7nWAR9YsOV&authuser=firas.ghani%40solid-run.com&usp=drive_fs
R77 R80 R81 R94 R99 R144 = RES1: RES SMD 10K OHM 1% 1/16W 0402; ASSEMBLY: DNI; BOM_IGNORE: TRUE; Category : Resistors (Size: 0402); Digikey P/N: 311-10.0KLRCT-ND; Manufacturer: YAGEO; Part Num#: RC0402FR-0710KL; Rating: 1/16W; SolidRun P/N: RE20013; Vol: 1%
R87 = RES1: RES SMD 200 OHM 1% 1/16W 0402; Category : Resistors (Size: 0402); Manufacturer: THYE MING; Part Num#: CR02FL6--200R; Rating: 1/16W; SolidRun P/N: RE20032; Vol: 1%
R88 = RES1: RES SMD 6.04K OHM 1% 1/16W 0402; Category : Resistors (Size: 0402); Digikey P/N: YAG2293CT-ND; Manufacturer: YAGEO; Part Num#: RC0402FR-076K04L; Rating: 1/16W; SolidRun P/N: RE20004; Vol: 1%
R95 R100 R145 = RES1: RES SMD 24K OHM 1% 1/16W 0402; Category : Resistors (Size: 0402); Digikey P/N: 541-24.0KLCT-ND; Manufacturer: VISHAY; Part Num#: CRCW040224K0FKED; Rating: 1/16W; SolidRun P/N: RE20038; Vol: 1%
TP1 TP2 = T_POINT_R: TEST POINT MINIATURE SMT; AGILE_PN: 510-75618; CAD_APPROVED: Yes; Category : Test Point; HEIGHT: 0.1MM; ROHS: Yes
U14 = IC-CYUSB3304-68LTXC: IC USB 3.0 HUB 4-PORT 68QFN IND; Category : IC-USB; Digikey P/N: 428-3333-ND; Manufacturer: Cypress Semiconductor Corp; SolidRun P/N: IC01686; Datasheet: https://www.cypress.com/file/141031/download
U16 U18 U36 = D-PCMF3USB3S: CMC 6LN SMD ESD USB 3.1, USB 2.0, HDMI 2.0, HDMI 1.4; Category : DI-TVS; Digikey P/N: 1727-2510-2-ND; Manufacturer: Nexperia USA Inc.; Rating: 7A; SolidRun P/N: DI00239; Vol: 5V(6/9); Datasheet: https://assets.nexperia.com/documents/data-sheet/PCMFXUSB3S_SER.pdf
U17 U19 U35 = IC-NX5P3090UK_WLCSP12: IC PWR SWITCH 1:1 12WLCSP; Category : IC-PWR-SW; Digikey P/N: 568-13049-2-ND; Manufacturer: NXP USA Inc; Rating: 3.3A; SolidRun P/N: IC01183; VOL: 5.5V; Datasheet: https://www.nxp.com/docs/en/data-sheet/NX5P3090.pdf
Y1 = XTAL-4P: 26MHz ±10ppm Crystal 12pF 60 Ohms; Category : OC-CRYSTAL; Digikey P/N: SER4186TR-ND; Manufacturer: EPSON; Rating: 12pF/10PPM; SolidRun P/N: OC00025; Datasheet: https://support.epson.biz/td/api/doc_check.php?dl=brief_FA-128_en.pdf

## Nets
GND: C11.2 C13.2 C14.2 C15.2 C17.2 C18.2 C19.2 C20.2 C21.2 C22.2 C23.2 C24.2 C26.2 C27.2 C29.2 C30.2 C32.2 C33.2 C34.2 C35.2 C36.2 C37.2 C38.2 C39.2 C40.2 C41.2 C42.2 C43.2 C44.2 C45.2 C46.2 C47.2 C76.2 C77.2 C78.2 C79.2 C80.2 C81.2 C82.2 C83.2 C84.2 C87.2 C88.2 C89.2 C90.2 C91.2 C92.2 C93.2 C95.2 C96.2 C97.2 C99.2 C100.2 C101.2 C108.2 C109.2 C110.2 C111.2 C114.2 C115.2 C116.2 C117.2 C191.2 C192.2 C193.2 C194.2 C200.2 C202.2 C203.2 C204.2 C205.2 C1224.2 C1226.2 C1233.2 C1235.2 D11.1 D13.1 D24.1 FB4.2 FB5.2 FB6.1 J2.6(VSS1) J2.G1 J2.G2 J2.G3 J2.G4 J3.A1(GND1) J3.A12(GND2) J3.B1(GND4) J3.B12(GND3) J27.4(GND) J27.7(GND) J27.13(GND) J27.16(GND) J5003.4(GND) J5003.7(GND_DRAIN) OC1.3(EMITTER) R12.2 R14.2 R19.1 R20.1 R23.1 R30.2 R41.1 R42.1 R43.1 R44.1 R46.2 R77.2 R80.2 R81.2 R87.1 R88.1 R95.2 R100.2 R145.2 R151.1 R154.2 R1159.1 R1162.1 R1173.2 R1174.2 R1223.2 R1224.2 SW1.1 SW2.1 U2.8(GND) U3.8(GND) U4.9(GND) U4.10(GND) U5.9(GND) U5.10(GND) U6.9(GND) U6.10(GND) U7.B1(GND) U8.2(GND) U8.9(NiC9/GND) U8.23(NiC23/GND) U8.32(NiC32/GND) U8.33(PAD) U9.4(GND) U10.3(AGND) U10.13(GND) U10.17(PAD) U11.2(~{OE}) U11.3(GND) U14.40(GND) U14.69(EPAD) U16.B1(GND_CH1) U16.B2(GND_CH2) U16.B3(GND_CH3) U17.B3(GND1) U17.C3(GND2) U17.D3(GND3) U18.B1(GND_CH1) U18.B2(GND_CH2) U18.B3(GND_CH3) U19.B3(GND1) U19.C3(GND2) U19.D3(GND3) U35.B3(GND1) U35.C3(GND2) U35.D3(GND3) U36.B1(GND_CH1) U36.B2(GND_CH2) U36.B3(GND_CH3) U39.8(GND) U41.9(GND) U41.10(GND) U42.9(GND) U42.10(GND) Y1.2 Y1.4 ; also on sheet 4 5 6 7 8 9 11
GND_SEC: C5.2 C6.2 C7.2 C8.2 D1.1(ANODE) FB4.1 M1.2(VDC-) M2.2(VDC-) Q1.1 Q1.2 Q1.3 R2.2 R3.2 R143.2
GNDC: FB5.1 FB6.2 J3.SH1 J3.SH2 J3.SH3 J3.SH4 J27.SH1 J27.SH2 J27.SH3 J27.SH4 J5003.S1 J5003.S2 J5003.S3 J5003.S4 SW1.SH1 SW1.SH2 SW1.SH3 SW2.SH1 SW2.SH2 SW2.SH3 ; also on sheet 5 6
VDD_1V2_FB: C1225.2 R1158.2 R1159.2 U41.8(FB)
VDD_1V8: C1233.1 C1234.1 R1161.1 S5.6 U42.5(VOUT) U42.6(VOUT) U42.7(VOUT) ; also on sheet 7
VDD_1V8_FB: C1234.2 R1161.2 R1162.2 U42.8(FB)
VDD_3V3: C24.1 C25.1 C35.1 C83.1 C84.1 C93.1 L7.1 R16.1 R24.1 R75.1 R76.1 R78.1 R79.1 R82.1 R83.1 R84.1 R85.1 R98.1 R101.1 R146.1 S5.5(A5) U4.5(VOUT) U4.6(VOUT) U4.7(VOUT) U7.A2(VIN) U14.56(AVDD33_6) U14.61(AVDD33_7) U14.66(AVDD33_8) ; also on sheet 4 5 6 7 8 11
VDD_3V3_FB: C25.2 R16.2 R19.2 U4.8(FB)
VDD_BOOT: R35.1 R36.1 R37.1 R38.1 S5.7(B6) S5.8(B5)
VDD_IO: C32.1 C33.1 C34.1 C38.1 C46.1 R25.1 R26.1 R27.2 R28.2 R29.2 R39.1 R40.1 R142.1 U8.8(NiC8/VDD) U8.22(VPS) U9.8(VCC) U11.6(VCCB) ; also on sheet 4 6 7 8 9 11
VDD_USB_1V2: C79.1 C80.1 C81.1 C82.1 C87.1 C88.1 C89.1 C90.1 C91.1 C92.1 C1224.1 C1225.1 L6.1 R1158.1 U14.7(DVDD12_4) U14.10(AVDD12_1) U14.13(DVDD12_5) U14.16(AVDD12_2) U14.34(AVDD12_3) U14.37(DVDD12_6) U14.43(DVDD12_7) U14.46(AVDD12_4) U14.49(DVDD12_8) U14.52(AVDD12_5) U14.53(AVDD12_6) U41.5(VOUT) U41.6(VOUT) U41.7(VOUT)
VIN: C11.1 C15.1 C200.1 R7.1 R9.1 U2.1(VIN) U3.1(VIN) U39.1(VIN) ; also on sheet 9
VIN+: D3.3(DC_OUT_PLUS) D4.3(DC_OUT_PLUS) D5.2(Cathod) F1.1
VIN-: D3.4(DC_OUT_MINUS) D4.4(DC_OUT_MINUS) D5.1(Anode) F2.1
VIN_5V: C16.1 C17.1 C18.1 C27.1 C30.1 L4.2 R10.1 U5.1(VIN) U5.2(VIN) U6.1(VIN) U6.2(VIN) ; also on sheet 7
VIN_BAT_CH: FB3.2 ; also on sheet 7 9
VIN_JACK: C1.1 C2.1 C3.1 C4.1 D6.2(ANODE) FB1.2 R1.1
VIN_VIDEO: C201.1 C202.1 C203.1 L12.2 R152.1 ; also on sheet 7
BOOT_MODE0: R41.2 S5.1(A1) ; also on sheet 6
BOOT_MODE1: R42.2 S5.2(A2) ; also on sheet 6
BOOT_MODE2: R43.2 S5.3(A3) ; also on sheet 6
BOOT_MODE3: R44.2 S5.4(A4) ; also on sheet 6
HUB_MODE0: R78.2 R81.1 U14.23(MODE_SEL[0])
HUB_MODE1: R79.2 U14.24(MODE_SEL[1])
HUB_RSTN: C99.1 R83.2 R86.2 U14.31(RESETN)
I2C2_SCL: U14.32(I2C_CLK) ; also on sheet 6 7
I2C2_SDA: U14.33(I2C_DATA) ; also on sheet 6 7
I2C3_SCL: U9.6(SCL) ; also on sheet 4 6 7 8 9
I2C3_SDA: U9.5(SDA) ; also on sheet 4 6 7 8 9
M2B_3V3: C26.1 C28.1 R18.1 U5.5(VOUT) U5.6(VOUT) U5.7(VOUT) ; also on sheet 4
M2M_3V3: C29.1 C31.1 R22.1 U6.5(VOUT) U6.6(VOUT) U6.7(VOUT) ; also on sheet 4
M.2B_3V3_EN: R1173.1 U5.3(EN) ; also on sheet 6
M.2M_3V3_EN: R1174.1 U6.3(EN) ; also on sheet 6
ONOFF: SW1.2 ; also on sheet 6
POE_AT: OC1.4(COLLECTOR) R142.2 ; also on sheet 6
POE_VIN_12V: C5.1 C6.1 C7.1 C8.1 D2.1(CATHODE) D6.1(CATHODE) FB3.1
Power Data+: D3.2(AC_IN) ; also on sheet 5
Power Data-: D3.1(AC_IN) ; also on sheet 5
Power Spare+: D4.2(AC_IN) ; also on sheet 5
Power Spare-: D4.1(AC_IN) ; also on sheet 5
RXD: R45.2 U10.15(TXD) U11.9(A2)
SD2_CLK: J2.5(CLK) ; also on sheet 6
SD2_CMD: J2.3(CMD) ; also on sheet 6
SD2_DATA0: J2.7(D0) ; also on sheet 6
SD2_DATA1: J2.8(D1) ; also on sheet 6
SD2_DATA2: J2.1(D2) ; also on sheet 6
SD2_DATA3: J2.2(CD/D3) ; also on sheet 6
SD2_nCD: J2.9(Cd) ; also on sheet 6
SD2_nRST: C37.1 R24.2 U7.B2(ON) ; also on sheet 6
SYS_nRST: SW2.2 ; also on sheet 6
TERMINAL_RX: R40.2 U11.4(B2) ; also on sheet 6
TERMINAL_TX: U11.5(B1) ; also on sheet 6
TPM_MISO: U8.24(MISO) ; also on sheet 6
TPM_MOSI: U8.21(MOSI) ; also on sheet 6
TPM_PIRQ#: R25.2 U8.18(~{SPI_PIRQ}) ; also on sheet 6
TPM_RST#: R26.2 U8.17(~{SPI_RST}) ; also on sheet 6
TPM_SCLK: U8.19(SPI_CLK) ; also on sheet 6
TPM_SS0: U8.20(~{SPI_CS}) ; also on sheet 6
TXD: U10.2(RXD) U11.8(A1)
USB1_DN: U36.A4(CH2_IN-) ; also on sheet 6
USB1_DP: U36.A3(CH2_IN+) ; also on sheet 6
USB1_PWR_EN: D12.2(ANODE) R99.2 R101.2 U19.A1(EN) ; also on sheet 6
USB1_RXN: U36.A1(CH1_IN+) ; also on sheet 6
USB1_RXP: U36.A2(CH1_IN-) ; also on sheet 6
USB1_TXN: C112.1 ; also on sheet 6
USB1_TXP: C113.1 ; also on sheet 6
USB1_VBUS: C116.1 C117.1 D13.2 J5003.1(VBUS) L10.2 ; also on sheet 6
USB2_DN: U14.58(US_DM) ; also on sheet 6
USB2_DP: U14.57(US_DP) ; also on sheet 6
USB2_RXN: C94.1 ; also on sheet 6
USB2_RXP: C85.1 ; also on sheet 6
USB2_TXN: C98.1 ; also on sheet 6
USB2_TXP: C86.1 ; also on sheet 6
USB2_VBUS: R76.2 R80.1 U14.17(VBUS_US) ; also on sheet 6
USB-HUB_RST#: R86.1 ; also on sheet 6
USB_5V0: C12.1 C13.1 C14.1 C23.1 C108.1 C109.1 C114.1 C115.1 C191.1 C192.1 C1226.1 C1235.1 L3.2 R8.1 R15.1 R94.1 R99.1 R144.1 R1157.1 R1160.1 U4.1(VIN) U4.2(VIN) U17.B1(VINT1) U17.B2(VINT2) U17.C1(VINT3) U19.B1(VINT1) U19.B2(VINT2) U19.C1(VINT3) U35.B1(VINT1) U35.B2(VINT2) U35.C1(VINT3) U41.1(VIN) U41.2(VIN) U42.1(VIN) U42.2(VIN) ; also on sheet 4 6 7 11
USB_HOST3_DN: J27.2(D1-) U16.C4(CH2_OUT-)
USB_HOST3_DP: J27.3(D1+) U16.C3(CH2_OUT+)
USB_HOST3_RXN: J27.5(SSRX1-) U16.C1(CH1_OUT+)
USB_HOST3_RXP: J27.6(SSRX1+) U16.C2(CH1_OUT-)
USB_HOST3_TXN: J27.8(SSTX1-) U16.C5(CH3_OUT+)
USB_HOST3_TXP: J27.9(SSTX1+) U16.C6(CH3_OUT-)
USB_HOST3_VBUS: C110.1 C111.1 D11.2 J27.1(VBUS1) L9.2
USB_HOST4_DN: J27.11(D2-) U18.C3(CH2_OUT+)
USB_HOST4_DP: J27.12(D2+) U18.C4(CH2_OUT-)
USB_HOST4_RXN: J27.14(SSRX2-) U18.C6(CH3_OUT-)
USB_HOST4_RXP: J27.15(SSRX2+) U18.C5(CH3_OUT+)
USB_HOST4_TXN: J27.17(SSTX2-) U18.C2(CH1_OUT-)
USB_HOST4_TXP: J27.18(SSTX2+) U18.C1(CH1_OUT+)
USB_HOST4_VBUS: C193.1 C194.1 D24.2 J27.10(VBUS2) L11.2
USB_HOSTDS1_DN: C106.2 ; also on sheet 7
USB_HOSTDS1_DP: C107.2 ; also on sheet 7
USB_HOSTDS2_DN: U14.63(DS2_DM) ; also on sheet 4
USB_HOSTDS2_DP: U14.62(DS2_DP) ; also on sheet 4
USB_HOSTDS3_DN: U14.64(DS3_DM) U16.A4(CH2_IN-)
USB_HOSTDS3_DP: U14.65(DS3_DP) U16.A3(CH2_IN+)
USB_HOSTDS4_DN: U14.68(DS4_DM) U18.A3(CH2_IN+)
USB_HOSTDS4_DP: U14.67(DS4_DP) U18.A4(CH2_IN-)
USB_HUB3_PWR_EN: D10.2(ANODE) R94.2 R98.2 U17.A1(EN) ; also on sheet 6
USB_HUB4_PWR_EN: D25.2(ANODE) R144.2 R146.2 U35.A1(EN) ; also on sheet 6
USB_MAIN_DN: J5003.2(D-) U36.C4(CH2_OUT-)
USB_MAIN_DP: J5003.3(D+) U36.C3(CH2_OUT+)
USB_MAIN_RXN: J5003.5(StdA_SSRX-) U36.C1(CH1_OUT+)
USB_MAIN_RXP: J5003.6(StdA_SSRX+) U36.C2(CH1_OUT-)
USB_MAIN_TXN: J5003.8(StdA_SSTX-) U36.C5(CH3_OUT+)
USB_MAIN_TXP: J5003.9(StdA_SSTX+) U36.C6(CH3_OUT-)
USB_VCCIO: C45.1 C47.1 R33.1 R45.1 U10.1(VCCIO) U10.8(3V3OUT) U11.7(VCCA)
USBDS1_RX_N: U14.50(DS1_RXM) ; also on sheet 7
USBDS1_RX_P: U14.51(DS1_RXP) ; also on sheet 7
USBDS1_TX_N: U14.48(DS1_TXM) ; also on sheet 7
USBDS1_TX_P: U14.47(DS1_TXP) ; also on sheet 7
USBDS2_RX_N: U14.44(DS2_RXM) ; also on sheet 4
USBDS2_RX_P: U14.45(DS2_RXP) ; also on sheet 4
USBDS2_TX_N: C63.2 ; also on sheet 4
USBDS2_TX_P: C64.2 ; also on sheet 4
USBDS3_RX_N: U14.36(DS3_RXM) U16.A1(CH1_IN+)
USBDS3_RX_P: U14.35(DS3_RXP) U16.A2(CH1_IN-)
USBDS3_TX_N: C1227.2 U16.A5(CH3_IN+)
USBDS3_TX_P: C1228.2 U16.A6(CH3_IN-)
USBDS4_RX_N: U14.14(DS4_RXM) U18.A6(CH3_IN-)
USBDS4_RX_P: U14.15(DS4_RXP) U18.A5(CH3_IN+)
USBDS4_TX_N: C196.2 U18.A2(CH1_IN-)
USBDS4_TX_P: C195.2 U18.A1(CH1_IN+)
V_DCJACK_IN: FB1.1 J1.2
V_SD: C36.1 J2.4(VDD) U7.A1(VOUT)
VIDEO_PWR_EN: R151.2 U39.2(EN) ; also on sheet 6
VUSB_IN: C41.1 C42.1 J3.A4(VBUS1) J3.A9(VBUS2) J3.B4(VBUS4) J3.B9(VBUS3) L5.1
N368204: FB2.1 J1.1
N368212: C1.2 C2.2 C3.2 FB2.2 Q1.5 Q1.6 Q1.7 Q1.8 Q1.9(PAD) R2.1
N432703: C43.1 C44.1 L5.2 U10.10(VCC)
N432793: C40.1 J3.A7(DN1) J3.B7(DN2) R31.1
N432805: R31.2 U10.7(USB_DM)
N432825: C39.1 J3.A6(DP1) J3.B6(DP2) R32.1
N432865: R32.2 U10.6(USB_DP)
N432869: R34.2 U10.16(RTS)
N432945: R34.1 U10.4(CTS)
N432967: R33.2 U10.9(Reset)
N858969: R29.1 U9.1(A0)
N858976: R28.1 U9.2(A1)
N858989: R27.1 U9.3(A2)
N961959: R30.1 U9.7(WP)
N1030509: C76.1 C77.1 C78.1 L6.2 U14.1(DVDD12) U14.3(DVDD12_2) U14.19(VDD_EFUSE) U14.27(DVDD12_3)
N1030566: C95.1 C96.1 C97.1 L7.2 U14.4(AVDD33_9) U14.28(VDD_IO)
N1211594: TP2.1(TP) U14.29(PWR_EN)
N18366817: R39.2 U11.1(T/~{R}2)
N18366859: R46.1 U11.10(T/~{R}1)
N18394145: C4.2 D1.3(CATHODE) Q1.4 R1.2
N18609057: C94.2 U14.5(US_TXM)
N18609067: C85.2 U14.6(US_TXP)
N18643625: C9.1 U2.6(BST)
N18643627: C9.2 L3.1 U2.9(SW)
N18643683: R7.2 U2.2(EN)
N18643723: C12.2 R8.2 R12.1 U2.3(FB)
N18643783: C20.1 R11.1 U2.4(COMP)
N18643851: C19.1 R11.2
N18712051: L1.2 M1.4(VIN+) M2.4(VIN+) OC1.1(ANODE)
N18712055: D2.2(ANODE) M1.1(VDC+) M2.1(VDC+)
N18712079: M1.3(ADJ) R3.1
N18712089: L2.2 M1.5(VIN-) M2.6(VIN-)
N18712233: F1.2 L1.1
N18712629: F2.2 L2.1
N18730185: C10.1 U3.6(BST)
N18730187: C10.2 L4.1 U3.9(SW)
N18730301: C16.2 R10.2 R14.1 U3.3(FB)
N18730347: C22.1 R13.1 U3.4(COMP)
N18730409: C21.1 R13.2
N18928862: R9.2 U3.2(EN)
N18929673: C28.2 R18.2 R20.2 U5.8(FB)
N18930783: C31.2 R22.2 R23.2 U6.8(FB)
N18932436: R15.2 U4.3(EN)
N19040498: L9.1 U17.C2(VBUS1) U17.D1(VBUS2) U17.D2(VBUS3)
N19040518: D10.1(CATHODE) U17.A2(~{FAULT})
N19040519: R95.1 U17.A3(ILIM)
N19040551: L10.1 U19.C2(VBUS1) U19.D1(VBUS2) U19.D2(VBUS3)
N19040571: D12.1(CATHODE) U19.A2(~{FAULT})
N19040572: R100.1 U19.A3(ILIM)
N19115590: M2.5(AT-DET) OC1.2(CATHODE)
N19116538: M2.3(ADJ) R143.1
N19170998: L11.1 U35.C2(VBUS1) U35.D1(VBUS2) U35.D2(VBUS3)
N19171160: D25.1(CATHODE) U35.A2(~{FAULT})
N19171162: R145.1 U35.A3(ILIM)
N19276391: C199.1 U39.6(BST)
N19276393: C199.2 L12.1 U39.9(SW)
N19276507: C201.2 R152.2 R154.1 U39.3(FB)
N19276553: C205.1 R153.1 U39.4(COMP)
N19276615: C204.1 R153.2
N19325753: C112.2 U36.A5(CH3_IN+)
N19325757: C113.2 U36.A6(CH3_IN-)
N19328184: R1157.2 U41.3(EN)
N19330776: C63.1 U14.42(DS2_TXM)
N19330779: C64.1 U14.41(DS2_TXP)
N19330847: C1227.1 U14.39(DS3_TXM)
N19330869: C1228.1 U14.38(DS3_TXP)
N19331053: C196.1 U14.12(DS4_TXM)
N19331056: C195.1 U14.11(DS4_TXP)
N19331248: C106.1 U14.59(DS1_DM)
N19331251: C107.1 U14.60(DS1_DP)
N19356015: R1160.2 U42.3(EN)
N19612596: R38.2 S5.12(B1)
N19612599: R36.2 S5.11(B2)
N19612602: R37.2 S5.10(B3)
N19612605: R35.2 S5.9(B4)
N20098910: J3.A5(CC1) R1224.1
N20098915: J3.B5(CC2) R1223.1
N105578872: C100.1 U14.54(XTL_OUT) Y1.1
N105578933: C101.1 U14.55(XTL_IN) Y1.3
N105579362: R84.2 U14.21(SWDDIO)
N105579373: R85.2 U14.22(SWDCLK)
N105704268: R82.2 U14.30(OVRCURR)
N105704492: TP1.1(TP) U14.20(SUSPEND)
N105704755: R87.2 U14.26(RREF_SS)
N105704758: R88.2 U14.2(RREF_USB2)
N105705743: C98.2 U14.8(US_RXM)
N105705746: C86.2 U14.9(US_RXP)
N106175198: R75.2 R77.1 U14.18(VBUS_DS)

Not connected (* = marked no-connect by the designer): D1 2(NC)*; J3 A2(SSTXP1) A3(SSTXN1) A8(SBU1) A10(SSRXN2) A11(SSRXP2) B2(SSTXP2) B3(SSTXN2) B8(SBU2) B10(SSRXN1) B11(SSRXP1); U2 5(PG)* 7(NC)*; U3 5(PG)* 7(NC)*; U4 4(PG); U5 4(PG); U6 4(PG); U8 1(NiC1/VDD)* 3(NiC3)* 4(NiC4)* 5(NiC5)* 6(GPIO)* 7(PP)* 10(NiC10)* 11(NiC11)* 12(NiC12)* 13(NiC13)* 14(NiC14/VDD)* 15(NiC15)* 16(NiC16/GND)* 25(NiC25)* 26(NiC26)* 27(NiC27)* 28(NiC28)* 29(NC29)* 30(NC30)* 31(NiC31)*; U10 5(CBUS2) 11(CBUS1) 12(CBUS0) 14(CBUS3); U14 25(GPIO); U39 5(PG)* 7(NC)*; U41 4(PG); U42 4(PG)

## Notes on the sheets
sheet 1
- Reverse Polarity
- 12V/1A
- 12V/2A
- VOUT= 0.8 x (1 + R1/R2)
- VOUT= 0.8 x (1 + R1/R2)
- Vin Max - 5.5V
- Vin Max - 5.5V
- Rfb
- Rfb
- 11.2V
- 10uH
- VOUT = 0.6 x (1 + Rb/Ra)
- Rfa
- VOUT = 0.6 x (1 + Rb/Ra)
- Rfa
- Vin Max - 5.5V
- Vin Max - 5.5V
- VOUT= 0.8 x (1 + R1/R2)
- Rfb
- Rfb
- VOUT = 0.6 x (1 + Rb/Ra)
- VOUT = 0.6 x (1 + Rb/Ra)
- Rfa
- Rfa
sheet 2
- micro SD connectors (assembly option of push-push type and hinged type)
- TPM
- 1.8 V or 3.3 V
  17.5 MA
- 1.7V to 3.6V
- DEBUG/Control PORT
- USB to RS-232
- +1.8V to +3.3V
- USB TYPE-C
- RESET button
- 1.8 V to 3.3 V
sheet 3
- 1,1 - Internal ROM
- Address 0x60
- Vin Max - 5.5V
- Rfb
- VOUT = 0.6 x (1 + Rb/Ra)
- Rfa
- ~2.1A Power Limit
- 2.1A
- ~2.1A Power Limit
- 2.1A
- ~2.1A Power Limit
- 2.1A
- Add control
